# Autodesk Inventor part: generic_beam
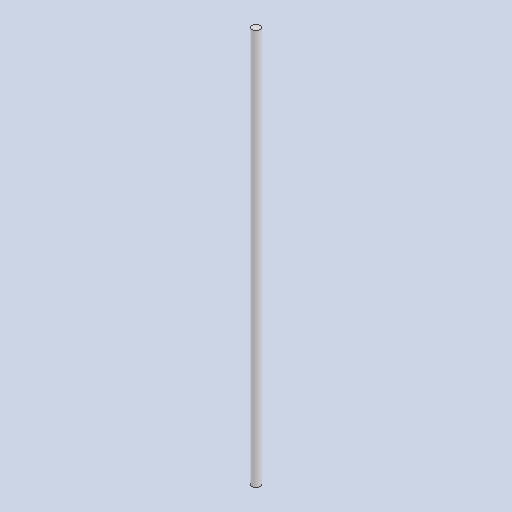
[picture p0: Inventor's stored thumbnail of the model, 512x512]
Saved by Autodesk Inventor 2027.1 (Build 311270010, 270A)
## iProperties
Created: 2026-07
Part Number: generic_beam
Material: Generic
Document SubType Name: Modeling
Designer: dunge
Density: 1 g/cm^3
Appearance: Default
Author: dunge
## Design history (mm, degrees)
sketch "Sketch1"
  geometry: L1 (-9.64, 0.476)-(-10.91, 0.476); L2 (-10.91, 0.476)-(-10.91, -0.794); L3 (-10.91, -0.794)-(-9.64, -0.794); L4 (-9.64, -0.794)-(-9.64, 0.476); C1 r 0.635 at (-10.275, -0.159); 1 further point
  constraints: 8 end point, 2 parallel, 1 centre point, 1 horizontal, 1 perpendicular
  dimensions: "d0" = 1.27 distance of L1.end L2.end; "d1" = 1.27 distance of L2.end L3.end
extrude "Extrusion1" new body sketch "Sketch1" distance "d2" = 63.5; taper "d3" = 0 deg
body "Solid1"
